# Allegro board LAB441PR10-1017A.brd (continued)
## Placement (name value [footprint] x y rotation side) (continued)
PL301  2.2UH_7.8A_20%_7X7X3_M  [L_7X7X3_M_2P]  66.72 63.83 180 bottom
PL303  HCB2012KF-121T50_0805  [TAI-T_HCB2012KF-121T50_2P]  68.78 54.88 180 top
PL304  3.3UH_6.3A_20%_7X7X3_M  [L_7X7X3_M_2P]  66.29 45.89 180 bottom
PL400  HCB1608KF-121T30_0603  [TAI-T_HCB1608KF-121T3_L0603_2P]  194.58 61.57 90 top
PL401  2.2UH_1239AS-H-2R2N-P2_1.3A_30%  [TOKO_1239AS-H-2R2N-P2_2P]  196.42 73.19 0 top
PL402  HCB1608KF-121T30_0603  [TAI-T_HCB1608KF-121T3_L0603_2P]  36.47 66.08 180 top
PL403  2.2UH_1239AS-H-2R2N-P2_1.3A_30%  [TOKO_1239AS-H-2R2N-P2_2P]  37.69 59.9 270 top
PL500  HCB2012KF-121T50_0805  [TAI-T_HCB2012KF-121T50_2P]  196.02 61.21 90 top
PL501  1UH_11A_20%_7X7X3_M  [L_7X7X3_M_2P]  203.52 57.35 180 bottom
PL600  HCB2012KF-121T50_0805  [TAI-T_HCB2012KF-121T50_2P]  89.05 52.93 180 top
PL601  2.2UH_7.8A_20%_7X7X3_M  [L_7X7X3_M_2P]  81.75 50.54 270 bottom
PL701  0.15UH_MMD06CZER15MG_37A_20%  [MAG_MMD06CZER15MG_4P]  96.17 55.83 90 bottom
PQ100  FDV301N_G_NL_SOT23-3  [FDV301N_NL_SOT23-3]  34.07 72.75 180 top
PQ101  MMST3904-7-F_SOT323  [MMST3904-7-F_SOT323-3]  31.4 70.2 90 top
PQ102  -  [2N7002KDWH_SOT363-6]  44.38 77.28 90 bottom
PQ103  -  [2N7002KDWH_SOT363-6]  45.98 72.74 90 top
PQ201  -  [CSD87312Q3E_SON8-4]  52.34 33.83 180 bottom
PQ202  -  [DCX124EK-7-F_SC74R-6]  42.63 35.6 90 bottom
PQ203  -  [SIR472DP-T1-GE3_POWERPAK8-5]  64.23 34.37 90 top
PQ204  -  [SI4835DDY-T1-E3_SO8]  70.05 39.02 0 bottom
PQ205  -  [SI7716ADN-T1-GE3_POWERPAK8-5]  58.79 32.44 270 top
PQ206  -  [DMN65D8LW-7_SOT323-3]  44.56 36.93 0 top
PQ300  -  [CSD87330Q3D_SON8-7]  66.78 56.51 180 bottom
PQ301  -  [CSD87330Q3D_SON8-7]  66.88 53.12 0 bottom
PQ409  -  [DMN66D0LDW-7_SOT363-6]  22.94 56.02 0 top
PQ500  -  [DMN65D8LW-7_SOT323-3]  195.34 63.19 180 bottom
PQ600  -  [MDV1528URH_PDFN33-8-5]  83.33 51.03 270 top
PQ601  -  [MDV1526URH_PDFN33-8-5]  81.65 51.71 180 top
PR100  100K_0402_5%  [R_0402]  65.4 20.91 0 top
PR101  0_0402_5%  [R_0402]  36.54 71.91 270 top
PR102  2.2K_0402_5%  [R_0402]  43.08 65.69 270 top
PR103  33_0402_5%  [R_0402]  36.54 70.18 270 top
PR104  100K_0402_1%  [R_0402]  30.39 72.79 0 top
PR105  10K_0402_1%  [R_0402]  33.04 68.91 0 top
PR106  15K_0402_1%  [R_0402]  31.3 71.88 180 top
PR107  4.7K_0805_5%  [R_0805]  38.44 76.91 90 top
PR108  1M_0402_1%  [R_0402]  44.84 76.4 270 top
PR109  3.3K_1206_5%  [R_1206]  32.16 75.26 0 top
PR110  1M_0402_1%  [R_0402]  43.97 76.36 180 top
PR111  10K_0402_1%  [R_0402]  47.21 76.33 90 bottom
PR112  1M_0402_1%  [R_0402]  42.59 78.27 180 bottom
PR113  100K_0402_1%  [R_0402]  47.21 78.23 90 bottom
PR114  200K_0402_1%  [R_0402]  36.29 74.68 90 top
PR116  1M_0402_1%  [R_0402]  43.97 75.47 180 top
PR202  0.01_1206_1%  [R_1206_4P-D]  58.98 40.46 180 bottom
PR203  4.7_0402_1%  [R_0402]  43.1 32.41 0 bottom
PR204  4.02K_0402_1%  [R_0402]  45.61 29.8 0 bottom
PR205  0_0402_5%  [R0402_0OHM]  45.64 30.68 180 top
PR206  0_0402_5%  [R0402_0OHM]  45.64 31.57 180 top
PR207  10_1206_5%  [R_1206]  47.27 36.46 270 top
PR208  4.02K_0402_1%  [R_0402]  45.61 29.8 0 top
PR209  34K_0402_1%  [R_0402]  46.52 28.91 180 bottom
PR210  6.49K_0402_1%  [R_0402]  47.77 29.8 0 bottom
PR211  2.2_0603_5%  [R_0603]  50.07 34.05 90 top
PR212  100K_0402_1%  [R_0402]  52.67 34 270 top
PR213  0_0402_5%  [R0402_0OHM]  45.61 28.91 0 top
PR214  0_0402_5%  [R0402_0OHM]  46.73 26.04 90 top
PR215  154K_0402_1%  [R_0402]  51.86 31.76 180 bottom
PR216  0_0402_5%  [R0402_0OHM]  50.19 24.72 90 top
PR217  0_0402_5%  [R0402_0OHM]  48.16 24.72 90 top
PR218  0_0402_5%  [R0402_0OHM]  49.31 24.72 90 top
PR219  0.01_1206_1%  [R_1206_4P-D]  71.66 38.27 180 top
PR220  4.02K_0402_1%  [R_0402]  53.93 29.67 0 top
PR221  4.7_1206_5%  [R_1206]  61.5 28.46 180 top
PR222  10_0603_1%  [R_0603]  54 28.59 0 top
PR223  1K_0402_1%  [R_0402]  52.67 34.86 90 top
PR224  0_0402_5%  [R0402_0OHM]  54.84 27.51 180 top
PR225  121K_0402_1%  [R_0402]  52.37 27.83 180 bottom
PR226  0_0402_5%  [R0402_0OHM]  51.97 24.72 90 top
PR227  0_0402_5%  [R0402_0OHM]  52.86 24.72 90 top
PR228  10K_0402_1%  [R_0402]  53.76 32.34 90 top
PR229  20K_0402_1%  [R_0402]  49.29 23.82 270 top
PR300  69.8K_0402_1%  [R_0402]  55.33 56.8 270 bottom
PR301  158K_0402_1%  [R_0402]  55.47 52.83 90 bottom
PR302  100K_0402_1%  [R_0402]  56.23 56.8 270 bottom
PR303  100K_0402_1%  [R_0402]  56.35 53.75 270 bottom
PR304  5.1K_0402_1%  [R_0402]  55.31 57.74 0 bottom
PR305  9.53K_0402_1%  [R_0402]  56.35 51.06 90 bottom
PR306  200_0402_1%  [R_0402]  58.46 51.2 180 bottom
PR307  0_0603_5%  [R_0603]  59.85 59.89 270 bottom
PR308  0_0603_5%  [R_0603]  60.48 51.26 270 bottom
PR309  4.7_0805_5%  [R_0805]  61.69 59.6 270 bottom
PR310  4.7_0805_5%  [R_0805]  63.56 49.95 90 bottom
PR311  100K_0402_1%  [R_0402]  54.45 56.8 270 bottom
PR312  0_0402_5%  [R_0402]  60.39 60.73 0 top
PR314  2.2K_0402_5%  [R_0402]  55.33 58.62 0 bottom
PR315  0_0402_5%  [R0402_0OHM]  59.45 53.37 180 top
PR319  1.91K_0402_1%  [R_0402]  21.82 57.81 270 top
PR400  0_0402_5%  [R_0402]  194.45 71.85 180 bottom
PR401  88.7K_0402_1%  [R_0402]  194.47 74.76 270 top
PR402  4.7_0805_5%  [R_0805]  196.3 67.73 270 top
PR403  100K_0402_1%  [R_0402]  193.61 73.85 90 top
PR404  100K_0402_5%  [R_0402]  196.28 76.63 90 top
PR405  0_0402_5%  [R_0402]  40.42 65.89 180 top
PR406  412K_0402_1%  [R_0402]  43.1 61.23 180 top
PR407  4.7_0805_5%  [R_0805]  35.83 59.56 180 top
PR408  324K_0402_1%  [R_0402]  42.18 63.01 0 top
PR409  100K_0402_5%  [R_0402]  41.12 60.05 0 top
PR410  0_0402_5%  [R0402_0OHM]  192.66 73.71 270 bottom
PR411  0_0402_5%  [R0402_0OHM]  38.57 67.71 270 top
PR412  0_0402_5%  [R0402_0OHM]  192.74 73.85 90 top
PR413  0_0402_5%  [R0402_0OHM]  42.18 63.9 0 top
PR445  232K_0402_1%  [R_0402]  29.3 61.98 90 top
PR447  1M_0402_1%  [R_0402]  29.94 57.53 90 top
PR448  10K_0402_1%  [R_0402]  29.05 57.53 90 top
PR449  1M_0402_1%  [R_0402]  26.33 58.37 180 top
PR450  10K_0402_1%  [R_0402]  23.21 60.33 90 top
PR451  82K_0402_1%  [R_0402]  30.29 63.76 90 top
PR452  22.1K_0402_1%  [R_0402]  24.66 68.53 0 top
PR455  10K_0402_1%  [R_0402]  26.33 57.48 180 top
PR456  82K_0402_1%  [R_0402]  27.27 58.45 270 top
PR457  232K_0402_1%  [R_0402]  29.3 61.11 270 top
PR458  42.2K_0402_1%  [R_0402]  27.02 66.04 90 top
PR460  48.7K_0402_1%  [R_0402]  27.91 66.96 270 top
PR461  0_0402_5%  [R0402_0OHM]  23.22 59.46 0 top
PR500  0_0402_5%  [R0402_0OHM]  203.6 60.4 0 top
PR501  1M_0402_1%  [R_0402]  203.6 61.29 0 bottom
PR502  4.7_1206_5%  [R_1206]  203.74 58.24 180 top
PR503  0_0603_5%  [R_0603]  201.96 64.47 180 top
PR504  0_0402_5%  [R_0402]  204.51 63.07 180 bottom
PR505  21K_0402_1%  [R_0402]  204.51 64.85 180 bottom
PR506  10K_0402_5%  [R_0402]  204.51 62.18 180 top
PR507  0_0402_5%  [R0402_0OHM]  203.6 62.18 0 bottom
PR508  35.7K_0402_1%  [R_0402]  203.6 63.96 0 bottom
PR509  127K_0402_1%  [R_0402]  203.6 63.97 0 top
PR510  100K_0402_5%  [R_0402]  196.37 65.21 270 bottom
PR511  0_0402_5%  [R_0402]  195.45 64.3 90 bottom
PR512  0_0402_5%  [R0402_0OHM]  204.51 63.1 180 top
PR600  2.2_0603_5%  [R_0603]  77.44 50.62 270 bottom
PR601  10.5K_0402_1%  [R_0402]  74.97 52.02 180 bottom
PR602  4.7_1206_5%  [R_1206]  77.82 49.04 90 top
PR603  5.1_0603_5%  [R_0603]  72.93 53.04 180 bottom
PR604  100K_0402_5%  [R_0402]  70.77 49.4 90 top
PR605  8.06K_0402_1%  [R_0402]  71.07 45.86 0 bottom
PR606  887K_0402_1%  [R_0402]  70.64 50.32 270 bottom
PR607  10K_0402_1%  [R_0402]  71.66 44.98 270 bottom
PR608  0_0402_5%  [R0402_0OHM]  72.56 49.93 180 top
PR609  0_0402_5%  [R0402_0OHM]  70.32 47.25 90 bottom
PR610  0_0402_5%  [R_0402]  69.31 48.16 270 bottom
PR700  75_0402_1%  [R_0402]  79.09 66.19 270 bottom
PR701  374K_0402_1%  [R_0402]  75.91 66.19 270 bottom
PR702  75_0402_1%  [R_0402]  75.02 66.19 270 bottom
PR703  681K_0402_1%  [R_0402]  74.13 66.19 270 bottom
PR704  36.5K_0402_1%  [R_0402]  73.25 66.19 270 bottom
PR705  10K_0402_5%  [R_0402]  78.2 63.27 270 top
PR706  56K_0402_1%  [R_0402]  77.31 63.27 270 top
PR707  150K_0402_1%  [R_0402]  76.42 63.27 270 top
PR708  100K_0402_1%  [R_0402]  75.52 63.28 270 top
PR709  20K_0402_1%  [R_0402]  74.64 63.27 270 top
PR710  39.2K_0402_1%  [R_0402]  79.09 63.27 270 top
PR711  10K_0402_5%  [R_0402]  79.98 66.19 270 bottom
PR713  1.91K_0402_1%  [R_0402]  73.07 61.04 180 bottom
PR714  2.2_0603_5%  [R_0603]  84.61 60.47 0 top
PR715  1_0603_5%  [R_0603]  71.91 58.62 90 bottom
PR716  0_0402_5%  [R0402_0OHM]  73.07 62.56 180 bottom
PR717  4.7_1206_5%  [R_1206]  93.31 59.26 270 top
PR718  3.3K_0402_1%  [R_0402]  80.04 57.37 270 bottom
PR719  10K_0402_5%  [R_0402]  81.83 58.24 180 bottom
PR720  4.75K_0402_1%  [R_0402]  81.82 57.37 270 bottom
PR721  10_0603_1%  [R_0603]  76.55 55.77 90 bottom
PR722  2.49K_0402_1%  [R_0402]  100.47 58.5 0 bottom
PR723  56_0402_5%  [R_0402]  75.47 54.1 90 bottom
PR724  11.5K_0402_1%  [R_0402]  101.39 59.39 180 bottom
PR725  2.94K_0402_1%  [R_0402]  101.39 60.28 180 bottom
PR726  54.9_0402_1%  [R_0402]  74.58 54.1 90 bottom
PR727  130_0402_1%  [R_0402]  73.69 54.1 90 bottom
PR728  0_0402_5%  [R0402_0OHM]  91.36 62.43 180 bottom
PR729  2M_0402_1%  [R_0402]  80.87 66.19 270 bottom
PR730  2M_0402_1%  [R_0402]  76.48 66.19 270 top
PR731  27K_0402_1%  [R_0402]  77.37 66.19 270 top
PR732  0_0805_5%  [R0805_0OHM]  90.71 52.42 180 bottom
PRP100  100_0804_8P4R_5%  [RP_0804_8P4R]  66.38 23.37 90 top
PU200  BQ24777RUYR_WQFN28_4x4  [BQ24777RUYR_WQFN28_4X4]  48.04 30.88 0 top
PU300  -  [TPS51285BRUKR_QFN20_3X3]  57.88 54.05 90 bottom
PU400  -  [TLV62150RGTR_QFN16_3X3]  194.89 70.06 90 top
PU401  -  [TLV62150RGTR_QFN16_3X3]  38.24 61.47 0 top
PU404  -  [LM393DMR2G_MICRO8]  26.04 60.19 0 top
PU405  -  [M74VHC1GT00DFT2G_SC70-5]  23.19 62.5 0 top
PU406  -  [M74VHC1GT00DFT2G_SC70-5]  23.45 70.37 0 top
PU500  -  [SY8206DQNC_QFN10_3X3]  202.15 61.93 90 bottom
PU600  -  [G5616ARZ1U_TQFN20_3X3]  74.3 47.29 180 bottom
PU700  -  [TPS51624RSM_QFN32_4X4]  74.83 59.7 90 bottom
PU701  -  [CSD97374CQ4M_SON8_3P5X4P5]  91.51 61.05 270 bottom
Q39  DII-DMN65D8LW-7~D  [SSM3K7002FU_SC70-3]  172.49 74.37 90 top
Q40  DII-DMN65D8LW-7~D  [SSM3K7002FU_SC70-3]  185.64 18.12 0 top
Q70  -  [AO4407AL_SO8]  186.91 47.87 0 bottom
Q71  DII-DMN65D8LW-7~D  [SSM3K7002FU_SC70-3]  191.29 43.13 90 top
Q305  DII-DMN65D8LW-7~D  [SSM3K7002FU_SC70-3]  191.29 40.72 90 top
Q360  SiSA12DN-T1-GE3_POWERPAK8-5  [SIS412DN-T1-GE3_POWERPAK8-5]  170.25 69.58 180 top
Q361  -  [SI1553CDL-T1-GE3_SC70-6]  167.84 72.84 0 top
Q362  DII-DMN65D8LW-7~D  [SSM3K7002FU_SC70-3]  169.7 76.79 270 top
QA1  -  [DMN66D0LDW-7_SOT363-6]  16.23 25.64 0 top
QA3  -  [DMN66D0LDW-7_SOT363-6]  17.52 33.71 180 top
QA6  DII-DMN65D8LW-7~D  [SSM3K7002FU_SC70-3]  23.36 35.86 180 top
QA7  LBSS138LT1G_SOT-23-3  [LBSS138LT1G_SOT23-3]  37.53 21.86 270 top
QA8  DII-DMN65D8LW-7~D  [SSM3K7002FU_SC70-3]  41.37 24.02 0 top
QA9  DII-DMN65D8LW-7~D  [SSM3K7002FU_SC70-3]  18.95 26.07 270 top
QC5  DII-DMN65D8LW-7~D  [SSM3K7002FU_SC70-3]  158.34 74.31 0 top
QE3  METR3904W-G_SC70-3  [MMBT3904WT1G_SC70-3]  131.54 59.2 270 top
QE4  METR3904W-G_SC70-3  [MMBT3904WT1G_SC70-3]  98.83 43.89 270 bottom
QE8  METR3904W-G_SC70-3  [MMBT3904WT1G_SC70-3]  188.49 77.84 180 top
QE9  -  [MMST3904-7-F_SOT323-3]  176.82 75.64 270 top
QE10  METR3904W-G_SC70-3  [MMBT3904WT1G_SC70-3]  152.56 40.72 270 top
QE11  METR3904W-G_SC70-3  [MMBT3904WT1G_SC70-3]  53.75 54.3 0 bottom
QE12  -  [DMN66D0LDW-7_SOT363-6]  177 78.04 90 top
QH6  -  [DMN66D0LDW-7_SOT363-6]  177.1 53.82 0 top
QH7  -  [DMN66D0LDW-7_SOT363-6]  192.7 15.99 270 top
QV2  LBSS138LT1G 1N_SOT-23-3  [LBSS138LT1G_SOT23-3]  22.48 57.04 90 bottom
R3  10K_0402_5%~D  [R_0402]  197.32 14.44 0 top
R7  10K_0402_5%~D  [R_0402]  21.21 21.47 180 bottom
R8  4.7K_0402_5%~D  [R_0402]  183.16 41.91 90 top
R9  4.7K_0402_5%~D  [R_0402]  182.27 41.91 90 top
R220  10K_0402_5%~D  [R_0402]  185.51 36.6 270 top
R222  0_0402_5%~D  [R_0402]  24.96 40 180 bottom
R249  0_0402_5%~D  [R_0402]  174.13 68.53 0 top
R250  0_0402_1%  [R0402_0OHM]  184.69 67.91 270 bottom
R251  0_0402_1%  [R0402_0OHM]  175.61 76.35 270 top
R252  0_0402_5%~D  [R_0402]  174.72 76.35 270 top
R253  0_0402_1%  [R0402_0OHM]  150.67 66.91 180 top
R262  0_0402_5%~D  [R_0402]  24.96 39.06 180 bottom
R268  0_0402_5%~D  [R_0402]  186.48 75.26 180 top
R269  0_0402_5%~D  [R_0402]  205.1 38.87 180 top
R270  0_0402_1%  [R0402_0OHM]  204.18 37.07 90 top
R271  0_0402_5%~D  [R_0402]  204.36 55.47 90 top
R272  0_0402_1%  [R0402_0OHM]  203.46 55.47 90 top
R290  100K_0402_5%~D  [R_0402]  53.05 56.8 270 bottom
R300  470_0402_5%  [R_0402]  173.25 72.58 90 top
R307  0.01_0603_1%  [R_0603]  164.42 57.13 0 top
R309  0_0603_5%  [R0603_0OHM]  168.01 54.89 180 top
R531  0_0603_5%~D  [R_0603]  185.51 45.1 270 bottom
R535  1M_0402_5%~D  [R_0402]  189.83 44.83 90 top
R536  100K_0402_5%~D  [R_0402]  190.72 45.75 270 top
R540  220K_0402_5%~D  [R_0402]  193.21 30.18 180 top
R541  820_0805_1%  [R_0805]  192.88 38.98 90 top
R545  220K_0402_5%~D  [R_0402]  193.21 29.29 180 top
R555  0_0402_5%~D  [R_0402]  22.58 50.43 180 bottom
R556  0_0402_5%~D  [R_0402]  22.58 51.32 180 bottom
R560  0_0402_5%~D  [R_0402]  23.09 46.62 180 bottom
R565  0_0402_5%~D  [R_0402]  23.09 47.51 180 bottom
R741  0_0402_5%~D  [R_0402]  31.65 36.87 0 bottom
R742  0_0402_5%~D  [R_0402]  31.65 35.85 0 bottom
R884  10K_0402_5%~D  [R_0402]  167.86 17.23 270 top
R886  10K_0402_5%~D  [R_0402]  165.57 18.25 0 top
R910  820_0402_5%~D  [R_0402]  11.32 8.08 0 top
R911  820_0402_5%~D  [R_0402]  6.66 9.08 180 top
R912  820_0402_5%~D  [R_0402]  6.66 8.13 180 top
R913  820_0402_5%~D  [R_0402]  6.66 7.18 180 top
R916  820_0402_5%~D  [R_0402]  6.66 6.22 180 top
R973  10K_0402_5%~D  [R_0402]  76.14 18.33 270 bottom
R974  0_0402_5%~D  [R_0402]  75.25 17.41 90 bottom
R1004  0_0402_5%~D  [R_0402]  70.29 68.09 180 bottom
R1005  0_0402_5%~D  [R_0402]  70.29 67.07 180 bottom
R1012  0_0402_5%~D  [R_0402]  70.6 69.97 180 bottom
R1013  0_0402_5%~D  [R_0402]  70.6 70.98 180 bottom
R1020  0_0402_5%~D  [R_0402]  170.86 62.56 180 bottom
R1021  0_0402_5%~D  [R_0402]  168.17 62.56 0 bottom
R1026  100K_0402_5%~D  [R_0402]  202.15 38 270 top
R1100  100K_0402_5%~D  [R_0402]  77.08 18.31 270 bottom
R1103  10K_0402_5%~D  [R_0402]  165.7 16.21 0 top
R1104  10K_0402_5%~D  [R_0402]  195.56 15.29 0 top
R1105  10K_0402_5%~D  [R_0402]  190.73 14.86 90 top
R1125  0_0603_5%  [R0603_0OHM]  29.82 37.16 270 top
R1131  0_0402_5%~D  [R_0402]  37.81 39.29 270 top
R1132  10K_0402_5%~D  [R_0402]  164.51 66.24 180 top
R1140  100K_0402_5%~D  [R_0402]  31.41 41.88 90 top
R1141  100K_0402_5%~D  [R_0402]  30.52 41.88 90 top
R1142  100K_0402_5%~D  [R_0402]  93.59 19.5 180 bottom
R1161  220K_0402_5%~D  [R_0402]  188.18 43.05 90 top
R1162  100K_0402_5%~D  [R_0402]  54.07 62.1 90 top
R1163  100K_0402_5%~D  [R_0402]  189.83 64.42 270 bottom
R1169  100K_0402_5%~D  [R_0402]  172.81 76.33 90 top
R1175  100K_0402_5%~D  [R_0402]  208.81 19.8 180 top
R1176  100K_0402_5%~D  [R_0402]  206.08 20.41 0 top
R1177  100K_0402_5%~D  [R_0402]  54.07 61.24 270 top
R1178  100K_0402_5%~D  [R_0402]  157.27 69.31 270 top
R1179  150_0402_5%~D  [R_0402]  107.67 66.12 180 top
R1180  1K_0402_5%~D  [R_0402]  113.01 78.34 270 bottom
R1181  100K_0402_5%~D  [R_0402]  204.93 26.49 0 top
R1185  100K_0402_5%~D  [R_0402]  154.83 60.78 0 bottom
R1186  100K_0402_5%~D  [R_0402]  41.29 53.74 0 top
R1187  100K_0402_5%~D  [R_0402]  173.02 69.55 180 top
R1188  0_0402_5%~D  [R_0402]  48.54 73.12 270 top
R1189  0_0402_1%  [R0402_0OHM]  206.77 30.01 90 top
R1190  0_0402_1%  [R0402_0OHM]  166.97 66.8 90 top
R1191  0_0402_5%~D  [R_0402]  160.33 44.1 270 top
R1198  1K_0402_5%~D  [R_0402]  71.02 79.59 270 top
R1199  0_0402_5%~D  [R_0402]  41.32 39.22 180 top
R1200  0_0402_5%~D  [R_0402]  39.97 43.99 270 top
R1203  100K_0402_5%~D  [R_0402]  44.42 43.99 270 top
R1208  0_0402_5%~D  [R_0402]  40.86 43.99 270 top
R1209  0_0402_5%~D  [R_0402]  47.59 43.99 270 top
R1210  0_0402_1%  [R0402_0OHM]  41.75 43.99 270 top
R1212  0_0402_1%  [R0402_0OHM]  42.64 43.99 270 top
R1216  1M_0402_5%~D  [R_0402]  29.02 45.11 270 top
R1228  0_0402_5%~D  [R_0402]  77.97 17.4 90 bottom
R1240  0.005_1206_1%  [R_1206]  150.08 76.53 270 top
R1242  0_0603_5%~D  [R_0603]  77.69 21.29 0 bottom
R1255  0_0402_5%~D  [R_0402]  43.53 43.99 270 top
R1299  100K_0402_5%~D  [R_0402]  186.15 21.17 180 top
R1309  0_0402_5%  [R_0402]  62.7 78.68 90 top
R1311  3K_0402_5%~D  [R_0402]  64.48 79.59 270 top
R1312  3K_0402_5%~D  [R_0402]  68.04 79.59 270 top
R1313  0_0402_5%~D  [R_0402]  41.32 40.11 180 top
R1314  0_0402_5%~D  [R_0402]  41.32 41 180 top
R1318  0_0603_5%  [R0603_0OHM]  32.86 36.87 270 top
R1320  0_0603_5%  [R0603_0OHM]  47.15 56.72 180 top
R1321  0_0805_5%  [R0805_0OHM]  201.39 31.64 270 top
R1322  0_0805_5%  [R0805_0OHM]  205.45 32.81 270 top
R1323  0_0603_5%  [R0603_0OHM]  200.63 18.38 180 top
R1324  10K_0402_5%~D  [R_0402]  86.02 72.47 180 bottom
R1325  10K_0402_5%~D  [R_0402]  84.24 72.47 180 bottom
R1326  0_0805_5%  [R0805_0OHM]  199.71 27.21 180 top
R1327  100K_0402_5%~D  [R_0402]  35.32 40.04 0 top
R1328  10K_0402_5%~D  [R_0402]  35.32 41 0 top
R1329  0_0805_5%  [R0805_0OHM]  36 55.89 180 top
R1330  0_0805_5%  [R0805_0OHM]  170.72 70.81 90 top
R1331  0_0805_5%  [R0805_0OHM]  166.69 58.38 90 top
R1332  0.01_0805_1%~D  [R_0805]  168.41 60.07 270 top
R1342  0_0805_5%  [R0805_0OHM]  201.01 23.25 0 top
R1343  0_0603_5%  [R0603_0OHM]  200.63 21.55 180 top
R1344  0_0805_5%  [R0805_0OHM]  36 52.21 180 top
R1353  0_0402_1%  [R0402_0OHM]  166.08 68.96 90 top
R1360  49.9K_0402_1%~D  [R_0402]  36.54 35.33 90 bottom
R1361  49.9K_0402_1%~D  [R_0402]  37.43 35.33 90 bottom
R1362  150K_0402_5%~D  [R_0402]  38.32 35.33 90 bottom
R1363  49.9K_0402_1%~D  [R_0402]  39.21 35.33 90 bottom
R1364  49.9K_0402_1%~D  [R_0402]  40.1 35.33 90 bottom
R1365  49.9K_0402_1%~D  [R_0402]  40.99 35.33 90 bottom
R1371  130_0402_1%  [R_0402]  105.43 66.56 0 bottom
R1372  49.9K_0402_1%~D  [R_0402]  52.89 66.56 90 top
R1373  49.9K_0402_1%~D  [R_0402]  49.89 66.55 90 top
R1374  49.9K_0402_1%~D  [R_0402]  50.91 66.55 90 top
R1375  49.9K_0402_1%~D  [R_0402]  51.91 66.55 90 top
R1376  10K_0402_5%~D  [R_0402]  182.97 46.13 270 bottom
R1377  10K_0402_5%~D  [R_0402]  182.08 45.21 90 bottom
R1379  330_0402_5%~D  [R_0402]  168.37 71.65 270 top
R1380  330_0402_5%~D  [R_0402]  167.48 71.65 270 top
R1381  10K_0402_5%~D  [R_0402]  169.21 75.77 180 top
R1393  0.01_0805_1%~D  [R_0805]  186.85 54.01 270 top
R1395  49.9K_0402_1%  [R_0402]  35.65 35.33 90 bottom
R1396  100K_0402_5%~D  [R_0402]  163.87 62.82 180 bottom
R2662  0_0402_5%~D  [R_0402]  181.2 45.21 90 bottom
R2669  0_0805_5%  [R0805_0OHM]  47.17 53.29 180 top
R2670  0_0603_5%  [R0603_0OHM]  48.61 60.15 180 top
R2671  0_0603_5%  [R0603_0OHM]  48.76 63.32 180 top
RA7  0_0402_1%  [R0402_0OHM]  160.06 69.29 180 bottom
RA8  0_0402_1%  [R0402_0OHM]  160.06 70.75 180 bottom
RA14  4.7K_0402_5%~D  [R_0402]  39.92 32.4 180 top
RA15  8.06_0402_1%  [R_0402]  17.3 28.32 270 bottom
RA16  100K_0402_5%~D  [R_0402]  16.87 21.1 90 top
RA17  8.06_0402_1%  [R_0402]  18.21 28.32 270 bottom
RA18  10K_0402_5%~D  [R_0402]  18.81 21.67 90 top
RA19  10K_0402_5%~D  [R_0402]  20.66 34.45 270 bottom
RA20  100K_0402_5%~D  [R_0402]  17.69 29.85 180 top
RA24  47K_0402_5%~D  [R_0402]  20.3 19.66 90 bottom
RA25  47K_0402_5%~D  [R_0402]  21.21 19.66 90 bottom
RA26  0_0402_1%  [R0402_0OHM]  16.78 30.79 0 top
RA27  2.2K_0402_5%~D  [R_0402]  12.72 22.14 270 bottom
RA28  2.2K_0402_5%~D  [R_0402]  12.72 23 90 bottom
RA29  0_0402_1%  [R0402_0OHM]  21.68 35.39 90 top
RA30  0_0402_1%  [R0402_0OHM]  19.75 33.53 90 bottom
RA31  0_0402_1%  [R0402_0OHM]  21.68 33.63 90 top
RA32  0_0402_5%~D  [R_0402]  21.91 22.13 90 top
RA35  100K_0402_5%~D  [R_0402]  16.36 30.42 180 bottom
RA36  0_0402_1%  [R0402_0OHM]  39.01 34.62 0 top
RA37  100K_0402_5%~D  [R_0402]  15.31 34.75 0 top
RA38  100K_0402_5%~D  [R_0402]  20.76 34.54 270 top
RA39  100K_0402_5%~D  [R_0402]  17.14 34.75 0 top
RA41  100K_0402_5%~D  [R_0402]  17.88 22.58 270 top
RA45  0_0402_1%  [R0402_0OHM]  33.88 22.63 270 top
RA48  4.7K_0402_5%~D  [R_0402]  23.37 31.17 0 bottom
RA49  4.7K_0402_5%~D  [R_0402]  26.23 31.53 270 bottom
RA50  1K_0402_5%~D  [R_0402]  23.43 29.71 0 bottom
RA51  1K_0402_5%~D  [R_0402]  25.29 30.62 90 bottom
RA52  0_0402_1%  [R0402_0OHM]  39.92 30.49 180 top
RA53  0_0402_1%  [R0402_0OHM]  39.92 31.45 180 top
RA54  0_0402_1%  [R0402_0OHM]  39.92 33.54 180 top
RA57  1K_0402_5%~D  [R_0402]  21 22.13 90 top
RA60  9.09K_0402_1%  [R_0402]  25.29 32.43 180 bottom
RA61  9.09K_0402_1%  [R_0402]  22.5 31.17 180 bottom
RA62  33_0402_5%~D  [R_0402]  37.76 33.54 180 top
RA75  200K_0402_1%  [R_0402]  39.92 29.54 180 top
RA76  100K_0402_1%~D  [R_0402]  37.75 28.7 90 top
RA80  0_0603_5%  [R0603_0OHM]  35.27 33.48 90 top
RA81  1M_0402_5%~D  [R_0402]  39.65 25.24 270 top
RA82  100K_0402_1%~D  [R_0402]  38.78 25.22 180 top
RA83  0_0603_5%  [R0603_0OHM]  26.13 36.46 270 top
RA84  0_0603_5%~D  [R_0603]  27.33 32.21 0 bottom
RA85  10K_0402_5%~D  [R_0402]  32.99 21.72 90 top
RA86  0_0402_1%  [R0402_0OHM]  38.78 24.33 180 top
RA87  1K_0402_5%~D  [R_0402]  35.84 22.63 270 top
RC9  1K_0402_5%  [R_0402]  157.61 44.92 180 bottom
RC36  24.9_0402_1%  [R_0402]  139.08 70.82 0 top
RC41  56_0402_5%  [R_0402]  109.52 65.19 0 top
RC43  62_0402_5%~D  [R_0402]  108.6 66.12 0 top
RC44  10K_0402_5%~D  [R_0402]  110.96 76.48 270 bottom
RC48  51_0402_5%  [R_0402]  105.43 68.72 0 bottom
RC52  51_0402_5%  [R_0402]  114.39 71.78 270 top
RC54  51_0402_5%  [R_0402]  115.28 71.78 270 top
RC55  200_0402_1%~D  [R_0402]  114.52 53.87 270 top
RC58  121_0402_1%~D  [R_0402]  112.77 51.44 0 top
RC60  100_0402_1%~D  [R_0402]  113.57 53.87 270 top
RC81  1K_0402_1%~D  [R_0402]  114.72 60.91 180 top
RC92  0_0402_1%  [R0402_0OHM]  103.43 64.66 0 bottom
RC93  75_0402_5%  [R_0402]  103.32 70.03 0 bottom
RC94  43_0402_5%~D  [R_0402]  103.47 67.34 270 bottom
RC96  0_0402_1%  [R0402_0OHM]  105.43 67.51 0 bottom
RC97  100_0402_1%~D  [R_0402]  113.12 71.78 270 top
RC98  0_0402_1%  [R0402_0OHM]  112.17 71.78 270 top
RC100  100_0402_1%~D  [R_0402]  110.27 70.87 90 top
RC146  0_0402_5%~D  [R_0402]  126.71 75.76 90 top
RC147  0_0402_1%  [R0402_0OHM]  126.71 77.61 180 top
RC148  0_0402_1%  [R0402_0OHM]  156.68 73.79 90 top
RC149  1K_0402_5%~D  [R_0402]  179.02 77.34 90 top
RC151  0_0402_1%  [R0402_0OHM]  112.22 69.29 0 top
RC152  0_0402_1%  [R0402_0OHM]  111.98 76.48 270 bottom
RC153  49.9_0402_1%~D  [R_0402]  112.35 62.82 0 top
RC154  49.9_0402_1%~D  [R_0402]  144.09 45.39 270 bottom
RC155  8.2K_0402_1%  [R_0402]  143.41 75.06 90 bottom
RC156  49.9_0402_1%~D  [R_0402]  144.97 45.39 270 bottom
RC158  0_0402_5%~D  [R_0402]  125.76 76.67 270 top
RC160  100K_0402_5%~D  [R_0402]  156.68 75.57 90 top
RC161  220K_0402_5%~D  [R_0402]  102.82 44.81 90 bottom
RC201  1.5K_0402_5%  [R_0402]  108.54 69.29 0 top
RD11  240_0402_1%  [R_0402]  168.62 22.06 270 top
RD12  240_0402_1%  [R_0402]  141.25 22.06 270 top
RD13  1.8K_0402_1%  [R_0402]  122.65 19.43 90 bottom
RD14  1.8K_0402_1%  [R_0402]  127.86 19.56 90 bottom
RD15  2.7_0402_1%~D  [R_0402]  124.43 20.35 270 bottom
RD16  1.8K_0402_1%  [R_0402]  123.54 20.35 270 bottom
RD17  240_0402_1%  [R_0402]  167.73 22.06 270 top
RD18  1.8K_0402_1%  [R_0402]  128.74 20.47 270 bottom
RD19  240_0402_1%  [R_0402]  140.3 22.06 270 top
RD20  4.99_0402_1%~D  [R_0402]  129.68 20.46 0 bottom
RD24  470_0402_5%~D  [R_0402]  144.49 43.84 270 top
RD25  34.8_0402_1%~D  [R_0402]  100.69 28.16 0 top
RD26  34.8_0402_1%~D  [R_0402]  154.32 32.46 0 top
RD27  34.8_0402_1%~D  [R_0402]  100.73 30.3 0 top
RD28  0_0402_1%  [R0402_0OHM]  145.38 43.84 270 top
RD29  240_0402_1%  [R_0402]  86.9 22.06 270 top
RD30  240_0402_1%  [R_0402]  95.15 22.06 270 top
RD31  240_0402_1%  [R_0402]  86.01 22.06 270 top
RD32  240_0402_1%  [R_0402]  94.26 22.06 270 top
RD33  34.8_0402_1%~D  [R_0402]  101.62 26.23 90 top
RD34  1.8K_0402_1%  [R_0402]  117.44 19.43 90 bottom
RD35  34.8_0402_1%~D  [R_0402]  154.53 21.74 270 top
RD36  34.8_0402_1%~D  [R_0402]  103.42 30.3 180 top
RD37  34.8_0402_1%~D  [R_0402]  104.23 21.24 270 top
RD38  34.8_0402_1%~D  [R_0402]  155.16 27.31 90 top
RD39  24.9_0402_1%  [R_0402]  132.43 20.47 270 bottom
RD40  24.9_0402_1%  [R_0402]  126.2 20.35 270 bottom
RD41  240_0402_1%  [R_0402]  152.68 22.06 270 top
RD42  240_0402_1%  [R_0402]  151.73 22.06 270 top
RD45  34.8_0402_1%~D  [R_0402]  103.42 28.53 180 top
RD46  34.8_0402_1%~D  [R_0402]  156.99 22.11 0 top
RD47  34.8_0402_1%~D  [R_0402]  105.12 21.24 270 top
RD48  34.8_0402_1%~D  [R_0402]  153.64 22.06 270 top
RD49  34.8_0402_1%~D  [R_0402]  155.24 24.91 180 top
RD50  34.8_0402_1%~D  [R_0402]  100.68 21.24 270 top
RD51  240_0402_1%  [R_0402]  115.16 22.06 270 top
RD52  240_0402_1%  [R_0402]  126.39 22.06 270 top
RD53  240_0402_1%  [R_0402]  114.2 22.06 270 top
RD54  240_0402_1%  [R_0402]  181.39 22.06 270 top
RD55  240_0402_1%  [R_0402]  125.51 22.06 270 top
RD56  240_0402_1%  [R_0402]  180.5 22.06 270 top
RD57  34.8_0402_1%~D  [R_0402]  155.08 23.83 0 top
RD58  34.8_0402_1%~D  [R_0402]  154.32 34.69 0 top
RD59  34.8_0402_1%~D  [R_0402]  99.79 21.24 270 top
RD60  34.8_0402_1%~D  [R_0402]  157.01 32.02 180 top
RD61  34.8_0402_1%~D  [R_0402]  103.42 31.19 180 top
RD62  34.8_0402_1%~D  [R_0402]  157.01 35.57 180 top
RD63  34.8_0402_1%~D  [R_0402]  102.52 26.67 90 top
RD64  34.8_0402_1%~D  [R_0402]  157.01 33.8 180 top
RD65  34.8_0402_1%~D  [R_0402]  103.42 33.86 180 top
RD66  34.8_0402_1%~D  [R_0402]  98.01 21.24 270 top
RD67  34.8_0402_1%~D  [R_0402]  103.41 26.67 90 top
RD68  34.8_0402_1%~D  [R_0402]  154.32 33.42 0 top
RD69  34.8_0402_1%~D  [R_0402]  100.73 33.86 0 top
RD70  34.8_0402_1%~D  [R_0402]  157.01 28.46 180 top
RD71  34.8_0402_1%~D  [R_0402]  155.08 22.94 0 top
RD72  34.8_0402_1%~D  [R_0402]  102.46 21.24 270 top
RD73  34.8_0402_1%~D  [R_0402]  155.24 25.8 180 top
RD74  34.8_0402_1%~D  [R_0402]  154.4 30.61 90 top
RD75  26.1_0402_1%~D  [R_0402]  101.66 37.42 180 top
RD76  26.1_0402_1%~D  [R_0402]  156.38 37.42 180 top
RD77  26.1_0402_1%~D  [R_0402]  101.66 36.4 180 top
RD78  26.1_0402_1%~D  [R_0402]  156.38 36.46 180 top
RD79  34.8_0402_1%~D  [R_0402]  103.42 34.75 180 top
RD80  34.8_0402_1%~D  [R_0402]  157.01 30.24 180 top
RD81  34.8_0402_1%~D  [R_0402]  157.01 34.69 180 top
RD82  34.8_0402_1%~D  [R_0402]  100.69 29.1 0 top
RD83  34.8_0402_1%~D  [R_0402]  103.34 21.24 270 top
RD84  34.8_0402_1%~D  [R_0402]  155.99 22.06 270 top
RD85  34.8_0402_1%~D  [R_0402]  98.9 21.24 270 top
RD86  34.8_0402_1%~D  [R_0402]  101.55 25.21 180 top
RD87  34.8_0402_1%~D  [R_0402]  100.73 34.75 0 top
RD88  34.8_0402_1%~D  [R_0402]  103.42 32.08 180 top
RD89  34.8_0402_1%~D  [R_0402]  154.32 35.57 0 top
RD90  34.8_0402_1%~D  [R_0402]  157.01 32.91 180 top
RD91  34.8_0402_1%~D  [R_0402]  156.87 24.54 270 top
RD92  30_0402_1%~D  [R_0402]  75.1 28.14 180 top
RD93  34.8_0402_1%~D  [R_0402]  156.68 25.78 90 top
RD94  34.8_0402_1%~D  [R_0402]  157.01 27.57 180 top
RD95  30_0402_1%~D  [R_0402]  170.4 22.06 270 top
RD96  34.8_0402_1%~D  [R_0402]  157.01 29.35 180 top
RD97  34.8_0402_1%~D  [R_0402]  103.42 32.97 180 top
RD98  34.8_0402_1%~D  [R_0402]  101.57 21.24 270 top
RD99  34.8_0402_1%~D  [R_0402]  103.42 29.41 180 top
RD100  34.8_0402_1%~D  [R_0402]  157.01 31.13 180 top
RD119  1.8K_0402_1%  [R_0402]  118.33 20.35 270 bottom
RD120  24.9_0402_1%  [R_0402]  121 20.35 270 bottom
RD121  4.99_0402_1%~D  [R_0402]  119.22 20.35 270 bottom
RE2  10K_0402_5%  [R_0402]  172.1 68.53 0 top
RE6  4.7K_0402_5%~D  [R_0402]  174.13 67.51 0 top
RE7  4.7K_0402_5%~D  [R_0402]  173.02 67.64 180 top
RE13  100K_0402_5%  [R_0402]  40.17 13.92 180 top
RE14  100K_0402_5%  [R_0402]  40.17 14.81 180 top
RE22  10K_0402_5%  [R_0402]  35.65 15.11 90 top
RE23  10K_0402_5%  [R_0402]  34.76 15.11 90 top
RE24  10K_0402_5%  [R_0402]  36.54 15.11 90 top
RE25  100K_0402_5%  [R_0402]  185.51 73.81 270 top
RE26  10_0402_5%  [R_0402]  186.4 73.81 270 top
RE27  10K_0402_5%  [R_0402]  33.88 15.11 90 top
RE31  100K_0402_5%  [R_0402]  190.47 61.37 270 top
RE32  0_0402_1%  [R0402_0OHM]  190.47 58.55 90 top
RE33  10K_0402_5%  [R_0402]  191.36 60.45 90 top
RE34  10K_0402_5%  [R_0402]  191.36 56.39 90 top
RE36  100K_0402_5%  [R_0402]  190.47 57.3 270 top
RE52  2.2K_0402_5%  [R_0402]  180.31 57.53 90 top
RE53  2.2K_0402_5%  [R_0402]  181.2 57.53 90 top
RE54  10K_0402_5%  [R_0402]  180.76 75.26 180 top
RE55  8.2K_0402_5%  [R_0402]  175.05 62.94 180 top
RE56  8.2K_0402_5%  [R_0402]  175.05 62.05 180 top
RE57  1K_0402_5%  [R_0402]  182.08 56.41 270 top
RE58  100K_0402_5%  [R_0402]  174.13 66.63 0 top
RE59  100K_0402_5%  [R_0402]  175.05 64.47 180 top
RE60  100K_0402_5%  [R_0402]  178.53 58.45 270 top
RE61  43_0402_5%  [R_0402]  175.05 60.28 180 top
RE62  0_0402_1%  [R0402_0OHM]  185.82 58.37 0 top
RE63  100K_0402_5%  [R_0402]  182.97 56.41 270 top
RE64  4.7K_0402_5%  [R_0402]  181.2 56.41 270 top
RE65  100K_0402_5%  [R_0402]  172.42 62.68 90 top
RE66  100_0402_1%  [R_0402]  173.02 65.36 180 top
RE67  10K_0402_5%  [R_0402]  189.76 62.31 0 top
RE68  100K_0402_5%  [R_0402]  173.83 76.35 270 top
RE69  8.2K_0402_5%  [R_0402]  177.04 73.92 270 top
RE70  2.2K_0402_5%  [R_0402]  178.91 73.03 90 top
RE71  2.2K_0402_5%  [R_0402]  189.76 63.2 0 top
RE72  10K_0402_5%  [R_0402]  173.58 65.41 90 bottom
RE73  2.2K_0402_5%  [R_0402]  189.76 64.09 0 top
RE74  10K_0402_5%  [R_0402]  174.46 65.41 90 bottom
RE75  100K_0402_5%  [R_0402]  175.35 65.41 90 bottom
RE76  49.9_0402_1%  [R_0402]  169.64 66.04 90 bottom
RE77  1.5K_0402_1%  [R_0402]  188.18 72.9 90 top
RE78  1K_0402_5%  [R_0402]  181.63 75.26 0 top
RE79  4.3K_0402_5%  [R_0402]  189.76 64.97 0 top
RE80  10_0402_5%  [R_0402]  179.93 73.03 90 top
RE81  10K_0402_5%  [R_0402]  192.24 58.55 90 top
RE82  10K_0402_5%  [R_0402]  191.36 58.55 90 top
RE83  10K_0402_5%  [R_0402]  178.08 78.49 90 top
RE84  100K_0402_5%  [R_0402]  174.02 77.85 90 top
RE85  10K_0402_5%  [R_0402]  177 66.32 270 bottom
RE86  10K_0402_5%  [R_0402]  187.29 64.42 270 bottom
RE87  1.5K_0402_5%  [R_0402]  175.86 54.59 270 top
RE88  1.5K_0402_5%  [R_0402]  178.58 56.68 180 top
RH2  10M_0402_5%  [R_0402]  167.8 51.91 270 bottom
RH3  10K_0402_5%~D  [R_0402]  192.35 17.43 180 top
RH4  10K_0402_5%  [R_0402]  106.76 69.29 0 top
RH5  10K_0402_5%~D  [R_0402]  195.55 14.39 0 top
RH11  1M_0402_5%~D  [R_0402]  151.35 44.32 90 top
RH12  10K_0402_5%~D  [R_0402]  166.34 48.37 0 top
RH21  0_0402_5%  [R_0402]  67.15 78.68 90 top
RH23  20K_0402_5%~D  [R_0402]  155.82 51.44 0 bottom
RH24  1K_0402_5%~D  [R_0402]  159.45 43.18 180 top
RH25  20K_0402_5%~D  [R_0402]  155.82 52.33 0 bottom
RH29  10K_0402_5%~D  [R_0402]  157.65 65.36 180 top
RH31  330K_0402_5%~D  [R_0402]  150.46 44.32 90 top
RH34  330K_0402_5%~D  [R_0402]  149.57 45.24 270 top
RH35  10K_0402_5%~D  [R_0402]  155.81 63.83 180 top
RH36  10K_0402_5%~D  [R_0402]  129.82 75.4 270 bottom
RH37  1K_0402_5%~D  [R_0402]  155.74 61.67 180 bottom
RH39  51_0402_5%  [R_0402]  109.82 57.34 90 top
RH40  51_0402_5%  [R_0402]  110.71 57.34 90 top
RH41  10K_0402_5%~D  [R_0402]  130.71 75.4 270 bottom
RH42  1K_0402_5%~D  [R_0402]  159.45 44.1 180 top
RH43  3K_0402_1%~D  [R_0402]  144.62 75.97 270 bottom
RH44  10K_0402_5%~D  [R_0402]  147.48 56.9 270 top
RH45  10K_0402_5%~D  [R_0402]  147.6 54.17 90 top
RH55  1K_0402_5%~D  [R_0402]  152.71 57.49 0 top
RH57  1K_0402_5%~D  [R_0402]  145.71 62.11 0 top
RH70  499_0402_1%~D  [R_0402]  158.01 52.27 0 top
RH72  499_0402_1%~D  [R_0402]  158.01 53.16 0 top
RH91  10K_0402_5%~D  [R_0402]  158.72 64.33 180 bottom
RH95  10K_0402_5%~D  [R_0402]  156.74 62.31 0 top
RH100  10K_0402_5%~D  [R_0402]  155.81 64.72 180 top
RH103  10K_0402_5%~D  [R_0402]  155.81 65.74 180 bottom
RH107  10K_0402_5%~D  [R_0402]  162.96 66.37 0 bottom
RH110  10K_0402_5%~D  [R_0402]  158.72 65.22 180 bottom
RH113  3K_0402_1%~D  [R_0402]  139.08 73.61 0 top
RH117  1M_0402_5%~D  [R_0402]  134.9 78.07 270 top
RH132  0_0402_1%  [R0402_0OHM]  163.49 61.04 180 bottom
RH133  0_0402_1%  [R0402_0OHM]  161.22 44.24 270 top
RH134  0_0402_5%~D  [R_0402]  172.61 61.45 0 bottom
RH135  0_0402_5%~D  [R_0402]  172.64 60.41 0 bottom
RH137  0_0402_1%  [R0402_0OHM]  166.34 47.46 0 top
RH146  1K_0402_5%~D  [R_0402]  161.33 59.64 180 bottom
RH147  330K_0402_5%~D  [R_0402]  156.77 46.5 180 bottom
RH154  1M_0402_5%~D  [R_0402]  163.02 44.35 270 top
RH159  10K_0402_5%~D  [R_0402]  162.12 44.26 270 top
RH163  22.6_0402_1%  [R_0402]  144.82 54.28 180 top
RH168  0_0402_5%~D  [R_0402]  160.38 66.31 180 top
RH171  100K_0402_5%~D  [R_0402]  160.38 67.2 180 top
RH180  10K_0402_5%~D  [R_0402]  157.8 63.45 0 bottom
RH183  10K_0402_5%~D  [R_0402]  160.32 62.31 180 top
RH196  10K_0402_5%~D  [R_0402]  163.87 63.7 180 bottom
RH197  10K_0402_5%~D  [R_0402]  160.77 59.56 180 top
RH198  10K_0402_5%~D  [R_0402]  161.33 66.37 180 bottom
RH199  10K_0402_5%~D  [R_0402]  161.33 68.4 180 top
RH200  10K_0402_5%~D  [R_0402]  163.87 69.04 180 bottom
RH248  8.2K_0402_5%~D  [R_0402]  160.42 64.59 0 bottom
RH270  1K_0402_5%~D  [R_0402]  162.96 59.26 0 bottom
RH271  10K_0402_5%~D  [R_0402]  158.16 71.07 180 top
RH294  10K_0402_5%~D  [R_0402]  157.75 53.54 0 bottom
RH297  0_0402_1%  [R0402_0OHM]  163.95 44.48 0 top
RH300  100K_0402_5%~D  [R_0402]  150.42 76.35 180 bottom
RH302  100K_0402_5%~D  [R_0402]  161.33 62.82 180 bottom
RH303  10K_0402_5%~D  [R_0402]  154.27 76.07 90 top
RH309  0_0402_1%  [R0402_0OHM]  155.11 43.18 90 top
RH314  10K_0402_5%~D  [R_0402]  157.24 70.18 0 top
RH315  10K_0402_5%~D  [R_0402]  154.89 63.45 0 bottom
RH316  10K_0402_5%~D  [R_0402]  155.16 76.99 270 top
RH338  3K_0402_1%~D  [R_0402]  139.04 76.29 180 bottom
RH340  0_0805_5%  [R0805_0OHM]  139.63 42.05 180 top
RH341  0_0603_5%  [R0603_0OHM]  147.48 47.45 180 top
RH346  0_0402_1%  [R0402_0OHM]  140.62 51.4 270 top
RH348  0_0603_5%  [R0603_0OHM]  161.73 49.03 180 top
RH350  0_0603_5%~D  [R_0603]  153.38 62.75 0 top
RH354  0_0603_5%  [R0603_0OHM]  151.68 62.58 270 top
RH355  0_0603_5%  [R0603_0OHM]  172.81 57.79 0 top
RH356  0_0603_5%  [R0603_0OHM]  171.8 57.79 180 top
RH357  0_0603_5%  [R0603_0OHM]  50.81 80.39 0 top
RH360  22_0402_5%~D  [R_0402]  144.37 52.86 270 top
RH363  1K_0402_5%  [R_0402]  55.52 77.04 0 top
RH367  1K_0402_5%  [R_0402]  55.52 76.15 0 top
RH369  0_0402_5%  [R_0402]  74.64 79.59 270 top
RH370  0_0402_5%  [R_0402]  86.02 76.02 180 bottom
RH371  0_0402_5%  [R_0402]  56.43 72.59 180 top
RH372  0_0402_5%  [R_0402]  56.43 71.71 180 top
RH373  0_0402_5%  [R_0402]  61.82 78.68 90 top
RH374  0_0402_5%  [R_0402]  60.04 78.68 90 top
RH382  100K_0402_5%~D  [R_0402]  158.01 51.36 0 top
RH383  100K_0402_5%~D  [R_0402]  161.33 65.48 180 bottom
RH392  10K_0402_5%~D  [R_0402]  154.22 60.78 180 top
RH393  10K_0402_5%~D  [R_0402]  157.65 63.83 180 top
RH394  10K_0402_5%~D  [R_0402]  147.72 46.05 0 top
RH395  10K_0402_5%~D  [R_0402]  169.94 61.67 0 bottom
RH397  10K_0402_5%~D  [R_0402]  155.81 66.63 180 top
RH400  100K_0402_5%~D  [R_0402]  157.75 54.43 90 bottom
RH401  100K_0402_5%~D  [R_0402]  156.75 44.1 270 top
RH405  0_0603_5%~D  [R_0603]  141.2 72.13 0 top
RH407  0_0603_5%~D  [R_0603]  142.83 63.98 270 top
RH408  0_0603_5%~D  [R_0603]  144.05 62.95 270 top
RH411  0_0402_5%  [R_0402]  60.93 78.68 90 top
RH412  0_0402_5%  [R_0402]  73.75 79.59 270 top
RH413  0_0402_5%  [R_0402]  75.59 79.59 270 top
RH414  0_0402_5%  [R_0402]  56.43 73.48 180 top
RH423  100K_0402_5%~D  [R_0402]  155.67 72.92 270 top
RH424  5.1K_0402_1%  [R_0402]  158.16 69.29 180 bottom
RH425  5.1K_0402_1%  [R_0402]  158.16 70.75 180 bottom
RH428  22_0402_5%~D  [R_0402]  144.62 47.14 270 top
RH430  0_0402_1%  [R0402_0OHM]  163.97 46.25 270 top
RH431  0_0402_5%~D  [R_0402]  155.67 74.7 270 top
RH434  1K_0402_5%~D  [R_0402]  155.81 71.71 180 bottom
RH435  1K_0402_5%~D  [R_0402]  154.89 70.75 0 bottom
RH438  1K_0402_5%~D  [R_0402]  56.38 69.44 90 bottom
RH440  100K_0402_5%~D  [R_0402]  154.89 67.51 0 top
RH441  100K_0402_5%~D  [R_0402]  154.83 71.07 0 top
RH442  SHORT PADS  [SHORTPADS]  155.35 68.59 0 top
RH443  SHORT PADS  [SHORTPADS]  155.35 69.93 0 top
RH444  0_0402_5%  [R_0402]  66.26 78.68 90 top
RH445  51_0402_5%  [R_0402]  111.6 57.34 90 top
RH446  0_0402_5%  [R_0402]  59.15 78.68 90 top
RH450  0_0402_1%  [R0402_0OHM]  154.86 58.99 0 bottom
RH451  0_0402_5%  [R_0402]  56.43 75.26 180 top
RH452  0_0402_1%  [R0402_0OHM]  148.63 45.16 180 top
RH453  0_0402_5%~D  [R_0402]  175.86 56.35 270 top
RH454  0_0402_5%~D  [R_0402]  179.42 53.72 90 top
RH455  0_0402_1%  [R0402_0OHM]  154.83 55.7 0 bottom
RH456  0_0402_5%~D  [R_0402]  194.25 13.69 180 top
RH457  49.9K_0402_1%~D  [R_0402]  163.87 67.26 180 bottom
RH458  49.9K_0402_1%~D  [R_0402]  154.83 69.29 0 bottom
RH459  49.9K_0402_1%~D  [R_0402]  154.83 68.4 0 bottom
RH460  49.9K_0402_1%~D  [R_0402]  163.87 68.15 180 bottom
RH461  0_0402_5%~D  [R_0402]  193.27 17.43 0 top
RH463  0_0402_1%  [R0402_0OHM]  155.34 57.35 0 bottom
RH465  1M_0402_5%~D  [R_0402]  160.42 69.42 0 top
RH466  10K_0402_5%~D  [R_0402]  154.89 64.34 0 bottom
RH467  10K_0402_5%~D  [R_0402]  161.26 66.3 90 top
RH474  0_0402_1%  [R0402_0OHM]  188.18 50.04 90 top
RH3527  0_0603_5%  [R0603_0OHM]  172.42 46.88 90 bottom
RH3530  10K_0402_5%~D  [R_0402]  154.83 62.56 0 bottom
RH3531  10K_0402_5%~D  [R_0402]  147.29 63.88 180 top
RH3532  10K_0402_5%~D  [R_0402]  162.96 65.48 0 bottom
RH3533  10K_0402_5%~D  [R_0402]  157.75 61.29 0 top
RH3534  10K_0402_5%~D  [R_0402]  157.6 66.71 180 top
RH3535  10K_0402_5%~D  [R_0402]  157.75 60.4 0 top
RH3536  10K_0402_5%~D  [R_0402]  157.75 59.51 0 top
RH3537  10K_0402_5%~D  [R_0402]  154.97 52.19 90 bottom
RH3538  10K_0402_5%~D  [R_0402]  158.01 54.05 0 top
RH3539  10K_0402_5%~D  [R_0402]  153.31 61.67 0 top
RH3540  10K_0402_5%~D  [R_0402]  161.33 67.26 180 bottom
RH3541  10K_0402_5%~D  [R_0402]  157.75 56.85 0 top
RH3542  10K_0402_5%~D  [R_0402]  157.75 58.62 0 top
RH3543  10K_0402_5%~D  [R_0402]  161.33 63.7 180 bottom
RH3544  10K_0402_5%~D  [R_0402]  149.39 65.61 180 top
RH3545  10K_0402_5%~D  [R_0402]  160.42 68.15 0 bottom
RH3546  10K_0402_5%~D  [R_0402]  157.75 55.96 0 top
RH3547  10K_0402_5%~D  [R_0402]  155.81 65.6 180 top
RH3548  10K_0402_5%~D  [R_0402]  163.87 64.59 180 bottom
RH3549  10K_0402_5%~D  [R_0402]  153.8 56.05 180 top
RP2  2.2K_0804_8P4R_5%  [RP_0804_8P4R]  158.78 58.87 180 bottom
RP4  10K_8P4R_5%  [RP_0804_8P4R]  158.78 67.95 180 bottom
RP5  33_8P4R_5%  [RP_0804_8P4R]  182.93 50.69 0 bottom
RP6  33_8P4R_5%  [RP_0804_8P4R]  184.11 49.35 180 bottom
RP7  33_8P4R_5%  [RP_0804_8P4R]  184.6 57.82 180 bottom
RP8  33_8P4R_5%  [RP_0804_8P4R]  182.92 53.51 0 bottom
RP13  10K_1206_10P8R_5%  [RP_1206_10P8R]  8.27 8.74 270 top
RP14  2.2K_0804_8P4R_5%  [RP_0804_8P4R]  146.66 78.76 270 bottom
RP15  33_8P4R_5%  [RP_0804_8P4R]  153.26 46.2 180 bottom
RP16  10K_8P4R_5%  [RP_0804_8P4R]  164.43 47.52 180 top
RP20  10K_8P4R_5%  [RP_0804_8P4R]  158.78 62.1 180 bottom
RP21  10K_8P4R_5%  [RP_0804_8P4R]  168.3 57.75 0 bottom
RPE5  100K_0804_8P4R_5%  [RP_0804_8P4R]  190.96 54.37 270 top
RPE7  10K_8P4R_5%  [RP_0804_8P4R]  170.92 66.06 270 bottom
RTCR1  1K_0402_5%~D  [R_0402]  10.13 10.16 90 top
RV2  100K_0402_5%~D  [R_0402]  22.17 67.12 270 top
RV3  100K_0402_5%~D  [R_0402]  20.4 67.1 270 top
RV4  5.1M_0402_5%  [R_0402]  15.97 66.19 90 top
RV8  0_0402_1%  [R0402_0OHM]  17.75 67.11 270 top
RV9  1M_0402_5%~D  [R_0402]  16.86 66.19 90 top
RV10  100K_0402_5%~D  [R_0402]  20.72 55.51 0 bottom
SW2  SKRBAAE010_4P  [SW_SKRBAAE010_4P]  190.53 75.98 0 top
SW3  TBFD12KQR_4P  [SW_NTC311-EA1T-A160T_4P]  4.02 23.28 270 top
SW4  SSAL120100_3P  [SW_SSAL120100_3P]  160.4 45.04 0 bottom
T2  PAD~D  [TPC12]  110.84 67.51 0 top
T123  PAD~D  [TPC12]  150.33 58.31 0 top
T124  PAD~D  [TPC12]  177.02 64.16 180 bottom
T125  PAD~D  [TPC12]  38.74 16.15 180 bottom
T226  PAD~D  [TPC12]  110.84 69.04 0 top
T227  PAD~D  [TPC12]  109.44 68.04 0 top
T228  PAD~D  [TPC12]  115.7 65.83 0 top
T229  PAD~D  [TPC12]  112.78 68.21 0 top
T230  PAD~D  [TPC12]  114.65 66.88 0 top
T231  PAD~D  [TPC12]  114.06 68.39 0 top
T263  PAD~D  [TPC12]  109.88 67.71 180 bottom
T264  PAD~D  [TPC12]  107.84 66.46 180 bottom
T265  PAD~D  [TPC12]  114.97 69.62 0 top
T266  PAD~D  [TPC12]  108.81 70.88 180 bottom
T267  PAD~D  [TPC12]  116.25 70.87 0 top
T268  PAD~D  [TPC12]  105.3 70 180 bottom
T269  PAD~D  [TPC12]  107.22 68.72 180 bottom
T273  PAD~D  [TPC12]  109.95 58.56 180 bottom
T275  PAD~D  [TPC12]  112.69 58.23 0 top
T276  PAD~D  [TPC12]  110.96 58.82 180 bottom
T277  PAD~D  [TPC12]  109.25 58.56 180 bottom
T278  PAD~D  [TPC12]  111.79 59.28 0 top
T279  PAD~D  [TPC12]  154.02 65.48 180 bottom
T281  PAD~D  [TPC12]  148.6 55.52 0 top
T282  PAD~D  [TPC12]  153.99 53.06 180 bottom
T284  PAD~D  [TPC12]  147.55 65.89 0 top
T286  PAD~D  [TPC12]  151.22 71.71 0 top
T287  PAD~D  [TPC12]  156.8 63.46 180 bottom
T288  PAD~D  [TPC12]  149.95 56.68 0 top
T289  PAD~D  [TPC12]  151.45 55.22 0 top
T290  PAD~D  [TPC12]  157.98 49.72 0 top
T291  PAD~D  [TPC12]  153.73 55.94 0 bottom
T292  PAD~D  [TPC12]  155.58 48.41 180 bottom
T293  PAD~D  [TPC12]  110.01 60.6 0 top
U34  -  [APE8937GN2_DFN8_2X2]  163.44 59.58 180 top
U48  -  [W25Q64FVSSIQ_SO8]  175.93 54.61 0 bottom
U652  AT97SC3205_TSSOP28~D  [AT97SC3205_TSSOP28]  178.37 44.68 0 top
U663  -  [74CBTLV3126DS_SSOP16]  87.97 74.31 90 bottom
U664  AOZ1331_DFN_14P  [TPS22966DPUR_SON14_2X3]  32.55 40.49 180 top
U671  -  [TXB0104PWR_TSSOP14]  49.85 69.79 0 top
U672  -  [74AUP1G07GW_TSSOP5]  164.83 69.42 180 top
U673  NCP4545IMNTWG_QFN18_3X3~D  [NCP4545IMNTWG_QFN18_3X3]  165.07 63.95 270 top
U675  -  [MC74VHC1G08DFT2G_SC70-5]  42.45 40.88 270 top
U679  NLSX0102FCT1G_FLIP CHIP8  [NLSX0102FCT1G_FLIP-CHIP8]  39.19 40.76 270 top
U682  S IC TC7SZ14FU SSOP 5P  [NL17SZ14DFT2G_SOT353-5]  153.24 72.41 0 top
U683  S IC TC7SZ14FU SSOP 5P  [NL17SZ14DFT2G_SOT353-5]  186.64 36.08 0 top
U697  -  [MC74VHC1G08DFT2G_SC70-5]  83.65 73.6 90 bottom
U699  MC74VHC1G32DFT2G_SC70-5~D  [MC74VHC1G32DFT2G_SC70-5]  28 46.9 270 top
U708  -  [SN74AUP1G04DCKR_SC70-5]  187.81 41.94 180 top
U715  AOZ1331_DFN_14P  [TPS22966DPUR_SON14_2X3]  203.98 35.27 180 top
U716  AOZ1331_DFN_14P  [TPS22966DPUR_SON14_2X3]  204.19 18.77 90 top
U717  AOZ1331_DFN_14P  [TPS22966DPUR_SON14_2X3]  203.3 24.66 90 top
U718  AOZ1331_DFN_14P  [TPS22966DPUR_SON14_2X3]  52.2 60.49 90 top
U719  AOZ1331_DFN_14P  [TPS22966DPUR_SON14_2X3]  50.68 54.01 90 top
U720  AOZ1331_DFN_14P  [TPS22966DPUR_SON14_2X3]  39.73 52.92 90 top
U726  -  [AP2337SA-7_SOT23-3]  26.88 65.72 270 bottom
U727  -  [W25Q32FVSSIQ_SO8]  187.06 58.23 0 bottom
U728  -  [G9091-330TO1U_TSOT-23-5]  47.26 79.31 270 top
UA2  -  [ALC3263-CG_QFN56_7X7]  35.01 25.35 90 top
UC1  -  [74AUP1G07GW_TSSOP5]  106.08 46.28 270 bottom
UC6  TC7SH08FU_SSOP5~D  [TC7SH08FU_SSOP5]  172.62 60.39 90 top
UCPU1  BDW_ULT_DDR3L/BGA  [SHARK-BAY-ULT_BGA_1168P-T]  151.6 72.28 0 bottom
UD1  MT41K256M16HA-125M:E_FBGA96  [MT41J256M16RE-15E-D_FBGA_96P]  160.3 36.65 0 top
UD3  MT41K256M16HA-125M:E_FBGA96  [MT41J256M16RE-15E-D_FBGA_96P]  144.59 36.65 0 top
UD4  MT41K256M16HA-125M:E_FBGA96  [MT41J256M16RE-15E-D_FBGA_96P]  172.94 36.65 0 top
UD7  MT41K256M16HA-125M:E_FBGA96  [MT41J256M16RE-15E-D_FBGA_96P]  131.98 36.65 0 top
UD28  MT41K256M16HA-125M:E_FBGA96  [MT41J256M16RE-15E-D_FBGA_96P]  78.39 36.65 0 top
UD29  MT41K256M16HA-125M:E_FBGA96  [MT41J256M16RE-15E-D_FBGA_96P]  91 36.65 0 top
UD31  MT41K256M16HA-125M:E_FBGA96  [MT41J256M16RE-15E-D_FBGA_96P]  106.71 36.65 0 top
UD32  MT41K256M16HA-125M:E_FBGA96  [MT41J256M16RE-15E-D_FBGA_96P]  119.35 36.65 0 top
UE4  -  [MCP23017T-E-ML_QFN28_6X6]  31.6 15.21 90 bottom
UE5  MEC5085-LZY-HST01_DQFN132_11X11  [MEC5085-LZY_DQFN132_11X11]  187.92 61.99 90 top
UH5  -  [MC74VHC1G08DFT2G_SC70-5]  159.4 63.38 0 top
US2  -  [G547I1P81U_MSOP8]  26.52 42.82 90 top
UV1  SN74CBT3257CPWR_TSSOP16~D  [SN74CBT3257CPWR_TSSOP16]  17.76 68.72 0 top
YE1  32.768KHZ 9PF Q13FC1350000300  [Y_Q13FC135000040_2P]  184.9 56.72 0 top
YH1  32.768KHZ_X1A000141000300  [Y_CM31532768DZFT_2P]  169.38 52.7 270 bottom
YH2  24MHZ_12PF_7V24000020  [Y_X3G024000DC1H_4P]  132.38 78.46 180 top

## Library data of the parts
C1-C7 C218 C219 C265 C352 C355 C375-C377 C612 C613 C621 C623 C713 C715 C720-C722 C963 C1060-C1069 C1102 C1134 C1137-C1142 C1145 C1158-C1167 C1169 C1199-C1204 C1208 C1211-C1225 C1227 C1228 C1230 C1231 C1237 C1241-C1244 C1247 C1254 C1256-C1258 C1264 C1273-C1275 C1278 C1281-C1286 C1289 C1292 C1293 C1297-C1302 C1304 C1309 C1321 C1322 C1324 C1325 C2973 C2982 C2983 CA3 CA5 CA23-CA29 CA31 CA33 CA34 CA40 CA49 CA53-CA57 CA68-CA71 CA78 CA80 CA86 CA88 CA91 CA97 CA100 CA103 CA104 CA106 CC233 CC234 CC238-CC240 CC243 CD5 CD35 CD37 CD39 CD40 CD42-CD44 CD46 CD51 CD52 CD54 CD56 CD58 CD60 CD66 CD68 CD70 CD72 CD76-CD79 CD82 CD84 CD85 CD87-CD96 CD129 CD132 CD133 CD135 CD136 CD139 CD140 CD142-CD144 CE3 CE10 CE13 CE14 CE17 CE21 CE22 CE38-CE41 CE43 CE44 CE46-CE68 CH1-CH7 CH11 CH16 CH23-CH26 CH39-CH41 CH47 CH82-CH85 CH95 CH102 CH1205-CH1207 CH1213-CH1216 CH1218 CH1219 CH1221 CH1222 CH1224 CH1226 CH1227 CH1229 CH1231-CH1236 CH1241-CH1249 CS42-CS44 CS57 CS58 CV2-CV14 CV798 MC3 MC29-MC33 PC100-PC102 PC104-PC107 PC110 PC201 PC203 PC204 PC207 PC211 PC216-PC218 PC225-PC227 PC302 PC303 PC305 PC306 PC314 PC323 PC400 PC402 PC404-PC408 PC410 PC412-PC415 PC428 PC429 PC433 PC434 PC500 PC503 PC504 PC515 PC600 PC601 PC610 PC612-PC614 PC700 PC701 PC705-PC707 PC709 PC712 PC715-PC718 PC823 = C_0402
C8 C712 C716 C719 C723 C962 C1143 C1209 C1240 CA42 CA48 CA74 CA82-CA85 CA87 CA90 CA92-CA96 CA105 CC160-CC165 CD41 CD45 CD47 CD50 CD55 CD57 CD59 CD61 CD67 CD69 CD71 CD73 CD80 CD81 CD83 CD86 CD101 CE4 CE42 CE45 CH1204 CH1217 CH1220 CH1223 CH1225 CH1239 CV1 PC51 PC103 PC109 PC200 PC202 PC205 PC210 PC219 PC223 PC224 PC228-PC230 PC300 PC309-PC312 PC324 PC502 PC505 PC513 PC514 PC604 PC607 PC611 PC708 PC710 PC711 PC713 PC714 = C_0603
C303 PC307 PC308 PC617 = C_B2
C1312-C1315 CA2 CA4 CA98 CA99 CA101 CA102 CV15 PC108 PC206 PC208 PC209 PC212-PC215 PC220-PC222 PC231-PC237 PC313 PC315 PC401 PC403 PC409 PC411 PC506 PC507 PC509-PC512 PC602 PC603 PC605 PC606 PC702 PC703 PC800-PC822 = C_0805
C2985 = C_1210
CH36 CH61 CH62 CH65 = C_A1
CLRP1 JTAG1 RH442 RH443 = SHORTPADS: User Part Number: PART#
CS59-CS62 PH700 PH701 PR100-PR106 PR108 PR110-PR114 PR116 PR203 PR204 PR208-PR210 PR212 PR215 PR220 PR223 PR225 PR228 PR229 PR300-PR306 PR311 PR312 PR314 PR319 PR400 PR401 PR403-PR406 PR408 PR409 PR445 PR447-PR452 PR455-PR458 PR460 PR501 PR504-PR506 PR508-PR511 PR601 PR604-PR607 PR610 PR700-PR711 PR713 PR718-PR720 PR722-PR727 PR729-PR731 R3 R7-R9 R220 R222 R249 R252 R262 R268 R269 R271 R290 R300 R535 R536 R540 R545 R555 R556 R560 R565 R741 R742 R884 R886 R910-R913 R916 R973 R974 R1004 R1005 R1012 R1013 R1020 R1021 R1026 R1100 R1103-R1105 R1131 R1132 R1140-R1142 R1161-R1163 R1169 R1175-R1181 R1185-R1188 R1191 R1198-R1200 R1203 R1208 R1209 R1216 R1228 R1255 R1299 R1309 R1311-R1314 R1324 R1325 R1327 R1328 R1360-R1365 R1371-R1377 R1379-R1381 R1395 R1396 R2662 RA14-RA20 RA24 RA25 RA27 RA28 RA32 RA35 RA37-RA39 RA41 RA48-RA51 RA57 RA60-RA62 RA75 RA76 RA81 RA82 RA85 RA87 RC9 RC36 RC41 RC43 RC44 RC48 RC52 RC54 RC55 RC58 RC60 RC81 RC93 RC94 RC97 RC100 RC146 RC149 RC153-RC156 RC158 RC160 RC161 RC201 RD11-RD20 RD24-RD27 RD29-RD42 RD45-RD100 RD119-RD121 RE2 RE6 RE7 RE13 RE14 RE22-RE27 RE31 RE33 RE34 RE36 RE52-RE61 RE63-RE88 RH2-RH5 RH11 RH12 RH21 RH23-RH25 RH29 RH31 RH34-RH37 RH39-RH45 RH55 RH57 RH70 RH72 RH91 RH95 RH100 RH103 RH107 RH110 RH113 RH117 RH134 RH135 RH146 RH147 RH154 RH159 RH163 RH168 RH171 RH180 RH183 RH196-RH200 RH248 RH270 RH271 RH294 RH300 RH302 RH303 RH314-RH316 RH338 RH360 RH363 RH367 RH369-RH374 RH382 RH383 RH392-RH395 RH397 RH400 RH401 RH411-RH414 RH423-RH425 RH428 RH431 RH434 RH435 RH438 RH440 RH441 RH444-RH446 RH451 RH453 RH454 RH456-RH461 RH465-RH467 RH3530-RH3549 RTCR1 RV2-RV4 RV9 RV10 = R_0402
D72 D73 D93 D116 = BAT54CW-7-F_SOT323-3
D81 DZ1-DZ4 = RB751S40T1G_SOD523-2
D122 = BAS40-04_SOT23-3
DA1 DA2 = AZ5125-02SPR7G_SOT23-3
DA3 DA4 = PJDLC05C_SOT23-3
DA5 DA7 = ESD207-B1-02EL_TSLP-2-19-2
DA6 = BAT54A-7-F_SOT23-3
DI1 = IP4292CZ10-TBR_XSON10_2P5X1
DI2-DI4 = L30ESDL5V0C3-2_SOT23-3
FD1-FD4 = FIDUCIAL_C40M80
H1 H4 H7 H9 H12 H13 H18 H19 = H_2P0
H3 = H_1P8N
H6 H10 H11 H14-H17 = H_3P3
H20-H22 H24 H25 = EMIST_SUL-12A2M_1P
H23 = H_2P3X1P8N
H26 = H_3P2X0P8
JAPS = ACES_50506-01841-P01_18P
JBATT1 = FOX_GS73091-10272-7H_9P-T
JCAM JTS = CVILU_CI1806M2HRP-NH_6P
JDEG1 JLPDE1 = HB_A531015-SCHR21_10P
JEDP = ACES_50398-04041-001_40P
JFAN1 JSPK1 = ACES_50224-00401-001_4P
JHP1 = SINGA_2SJ3095-022111F_6P-T
JIO1 = JXT_FP270H-061G1AM_61P
JKB1 = E-T_6710K-Y15M-31L_15P
JMDP = TE_C-PT13-061_20P-T
JNFC1 = E-T_6705K-Y15N-00L_15P
JNGFF1 = CONCR_213EBAA2FKA_67P
JNGFF3 = CONCR_213MAAA32FA_67P-T
JP100 = ACES_88266-05001_5P
JPA1-JPA5 PJP14 PJP15 PJP200 PJP400 PJP401 PJP602 = JUMP_43X39
JRTC1 = ACES_50278-00201-001_2P
JTP1 = E-T_6705K-Y08N-40L_8P
JUSB1 = TE_C-PT13-067_9P-T
JXDP = SAMTE_BSH-030-01-L-D-A_60P
L2-L5 = MURAT_BLM15PX181SN1D_2P
L55 ML9-ML11 = MURAT_DLW21HN900HQ2L_4P
L56-L60 = INPAQ_HCM1012GH900BP_4P
L61-L63 LH10-LH12 = MURAT_LQM2MPN2R2NG0L_2P
LA1 LA2 = MURAT_BLM15PX600SN1D_2P
LA3 = MURAT_BLM21PG600SN1D_L0805_2P
LA4 LA5 PR205 PR206 PR213 PR214 PR216-PR218 PR224 PR226 PR227 PR315 PR410-PR413 PR461 PR500 PR507 PR512 PR608 PR609 PR716 PR728 R250 R251 R253 R270 R272 R1189 R1190 R1210 R1212 R1353 RA7 RA8 RA26 RA29-RA31 RA36 RA45 RA52-RA54 RA86 RC92 RC96 RC98 RC147 RC148 RC151 RC152 RD28 RE32 RE62 RH132 RH133 RH137 RH297 RH309 RH346 RH430 RH450 RH452 RH455 RH463 RH474 RV8 = R0402_0OHM
LA6 LA7 = CHILI_PBY100505T-600Y-N_2P
LA14 = MURAT_BLM15BB220SN1D_2P
LED10-LED14 = LED_27-11-T1D-CP1Q1RY-3C_2P
MD5 MD16 = TVWDF1004AD0_DFN9
MD9 MD10 = PESD5V0U2BT_SOT23-3
ML12 ML13 = MURAT_DLW21SN670HQ2L_4P
PC609 = C_B
PC704 = C_D2
PD100 PD101 = TVNST52302AB0_SOT523-3
PD102 = AZ5125-01HPR7G_SOD523-2
PD200 PD201 = SDMK0340L-7-F_SOD323-2
PJP300 PJP301 PJP500 PJP600 PJP601 = JUMP_43X118
PL100 PL101 PL103 PL104 PL200 PL300 PL303 PL500 PL600 = TAI-T_HCB2012KF-121T50_2P
PL102 = MURAT_BLM15AG102SN1D_2P
PL201 PL301 PL304 PL501 PL601 = L_7X7X3_M_2P
PL400 PL402 = TAI-T_HCB1608KF-121T3_L0603_2P
PL401 PL403 = TOKO_1239AS-H-2R2N-P2_2P
PL701 = MAG_MMD06CZER15MG_4P
PQ100 = FDV301N_NL_SOT23-3
